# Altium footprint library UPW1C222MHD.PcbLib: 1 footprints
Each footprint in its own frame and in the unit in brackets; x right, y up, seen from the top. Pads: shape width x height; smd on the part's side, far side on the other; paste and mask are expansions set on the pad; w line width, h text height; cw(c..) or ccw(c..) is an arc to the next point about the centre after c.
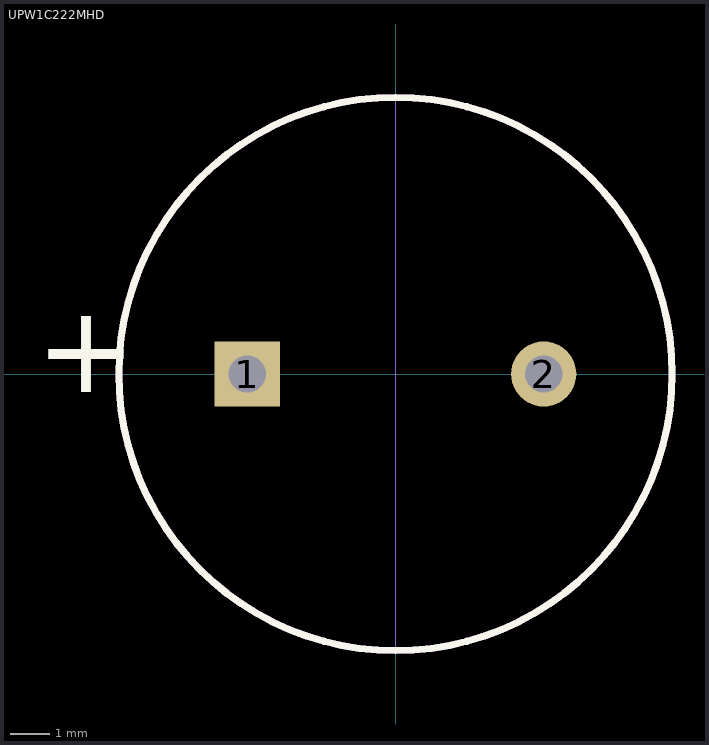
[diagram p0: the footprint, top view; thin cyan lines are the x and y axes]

## UPW1C222MHD [mil] "12.5Dx25T-5mmLS"
height 1062.99
pads (2):
  rect 65x65 hole 37: 1(-147.64,0)
  round 65 hole 37: 2(147.64,0)
Top Overlay:
  circle w7: c0,0 r275.59
  text "+" at -358.27,-47.24 h150
M5 Assembly Top:
  circle w7: c0,0 r275.59
  text "+" at -358.27,-47.24 h150
  text ".Designator" at -165.35,-15.75 h72.83
M13 Component Bodies Top:
  lines w1: 0,-275.59 ccw(c0,0) 0,275.59 0,-275.59
3D body: height 1066.93, standoff 1062.99, extent -0.02,-275.61 275.61,275.61
3D body: height 1062.99, standoff 0, extent -275.58,-275.58 275.6,275.6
